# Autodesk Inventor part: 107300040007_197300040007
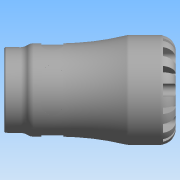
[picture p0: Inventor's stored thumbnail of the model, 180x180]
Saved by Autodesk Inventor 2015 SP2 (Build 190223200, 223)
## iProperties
Created: 2016-12
Part Number: 107300040007_197300040007
Material: Generic
Description: PLASSON FEMALE INTEGRAL BRASS THREAD 40X3/4" SERIES 1
Document SubType Name: Modeling
Designer: KIM
Density: 1 g/cm^3
Appearance: Default
Author: KIM
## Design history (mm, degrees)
derived "1073.ipt"
feature "Solid1::1073.ipt"
tag "TaggingFeature1"
body "Solid1"
other parameters: "d0" = 109, "d1" = 30.66, "d6" = 73, "d8" = 59.5, "d13" = 8, "d14" = 8, "d15" = 0, "d17" = 360 deg, "d19" = 8 deg, "d20" = 0.8, "d21" = 0.8, "d22" = 8 deg, "d24" = 0, "d26" = 360 deg, "d32" = 7, "d33" = 7, "d39" = 0.72351, "d42" = 24.117, "d43" = 54.6, "d46" = 3.33333, "d47" = 16, "d48" = 22.91115, "d50" = 6.6, "d51" = 0.7, "d54" = 14, "d55" = 8.8, "d57" = 15.68, "d58" = 0, "d68" = 360 deg, "d72" = 0.8, "d74" = 0, "d76" = 11.9, "H_" = 109, "l_" = 73, "G_" = 24.117, "l_2" = 16, "d9" = 10
